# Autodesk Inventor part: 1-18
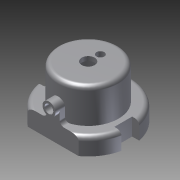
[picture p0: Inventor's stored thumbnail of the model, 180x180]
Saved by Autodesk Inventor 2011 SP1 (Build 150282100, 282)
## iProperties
Created: 2014-02
Part Number: 1-18
Document SubType Name: Modeling
Designer: Administrator
Density: 1 g/cm^3
Author: Administrator
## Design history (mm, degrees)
sketch "草图1"
  geometry: L1 (-5.876, -8.091)-(5.876, -8.091); L2 (8.154, 2.016)-(9.795, 2.016); L3 (8.154, 2.016)-(8.154, -2.106); L4 (8.154, -2.106)-(9.776, -2.106); L5 (-9.776, -2.106)-(-8.065, -2.106); L6 (-8.065, -2.106)-(-8.065, 2.02); L7 (-8.065, 2.02)-(-9.794, 2.02); A1 r 10 centre (0, 0) between (9.795, 2.016) and (-9.794, 2.02); A2 r 10 centre (0, 0) between (-9.776, -2.106) and (-5.876, -8.091); A3 r 10 centre (0, 0) between (5.876, -8.091) and (9.776, -2.106); 1 further point
  constraints: 14 end point, 6 point on circle, 3 centre point, 3 perpendicular, 2 parallel, 1 coincident, 1 collinear, 1 horizontal
extrude "拉伸1" new body sketch "草图1" distance "d1" = 4; taper "d2" = 0 deg
sketch "草图2"
  geometry: C1 r 7 at (0, 0); A1 r 10 centre (0, 0) between (9.795, 2.016) and (-9.794, 2.02) reference
  constraints: 1 centre point, 1 coincident
  dimensions: "d3" = 14 diameter of C1
extrude "拉伸2" join sketch "草图2" distance "d4" = 8; taper "d5" = 0 deg
fillet "圆角1" dims "d6" = 1
sketch "草图3"
  geometry: C1 r 6 at (0, 0) reference; C2 r 5 at (0, 0)
  constraints: 1 centre point, 1 coincident
  dimensions: "d7" = 10 diameter of C2
extrude "拉伸3" cut sketch "草图3" distance "d8" = 2; taper "d9" = 0 deg
sketch "草图4"
  geometry: C1 r 5 at (0, 0) reference; C2 r 4 at (0, 0)
  constraints: 1 centre point, 1 coincident
  dimensions: "d10" = 8 diameter of C2
extrude "拉伸4" cut sketch "草图4" distance "d11" = 9; taper "d12" = 0 deg
sketch "草图5"
  geometry: C1 r 4 at (0, 0) reference; C2 r 1.5 at (0, 0); C3 r 0.9 at (0, 2.824)
  constraints: 2 centre point, 1 coincident
  dimensions: "d13" = 3 diameter of C2; "d14" = 1.8 diameter of C3
extrude "拉伸5" cut sketch "草图5" stored distance "d15" = 1.8 (= d14); taper "d16" = 0 deg
sketch "草图6"
  geometry: L1 (11.753, 4)-(0, 4) reference; L2 (4.376, 7)-(4.376, 4); L3 (7.376, 7)-(7.376, 4); A1 r 1.5 centre (5.876, 7) between (7.376, 7) and (4.376, 7); 1 further point
  constraints: 4 end point, 2 perpendicular, 2 point on circle, 2 point on line, 2 tangent, 1 centre point
  dimensions: "d18" = 3 diameter of A1
extrude "拉伸6" join sketch "草图6" stored distance "d19" = 1.8 (= d14); taper "d20" = 0 deg
fillet "圆角2" dims "d21" = 1
sketch "草图7"
  geometry: A1 r 1.5 centre (5.876, 7) between (7.376, 7) and (4.376, 7) reference; 2 further points
  constraints: 1 coincident, 1 horizontal alignment, 2 other
extrude "拉伸7" join sketch "草图7" distance "d23" = 1; taper "d24" = 0 deg
sketch "草图8"
  geometry: C1 r 1.5 at (0, 0) reference; C2 r 1 at (0, 0); 1 further point
  constraints: 1 centre point, 1 coincident
  dimensions: "d25" = 2 diameter of C2
extrude "拉伸8" cut sketch "草图8" stored distance "d26" = 1; taper "d27" = 0 deg
fillet "圆角3" dims "d28" = 1
fillet "圆角4" dims "d29" = 1
node "实体1"
